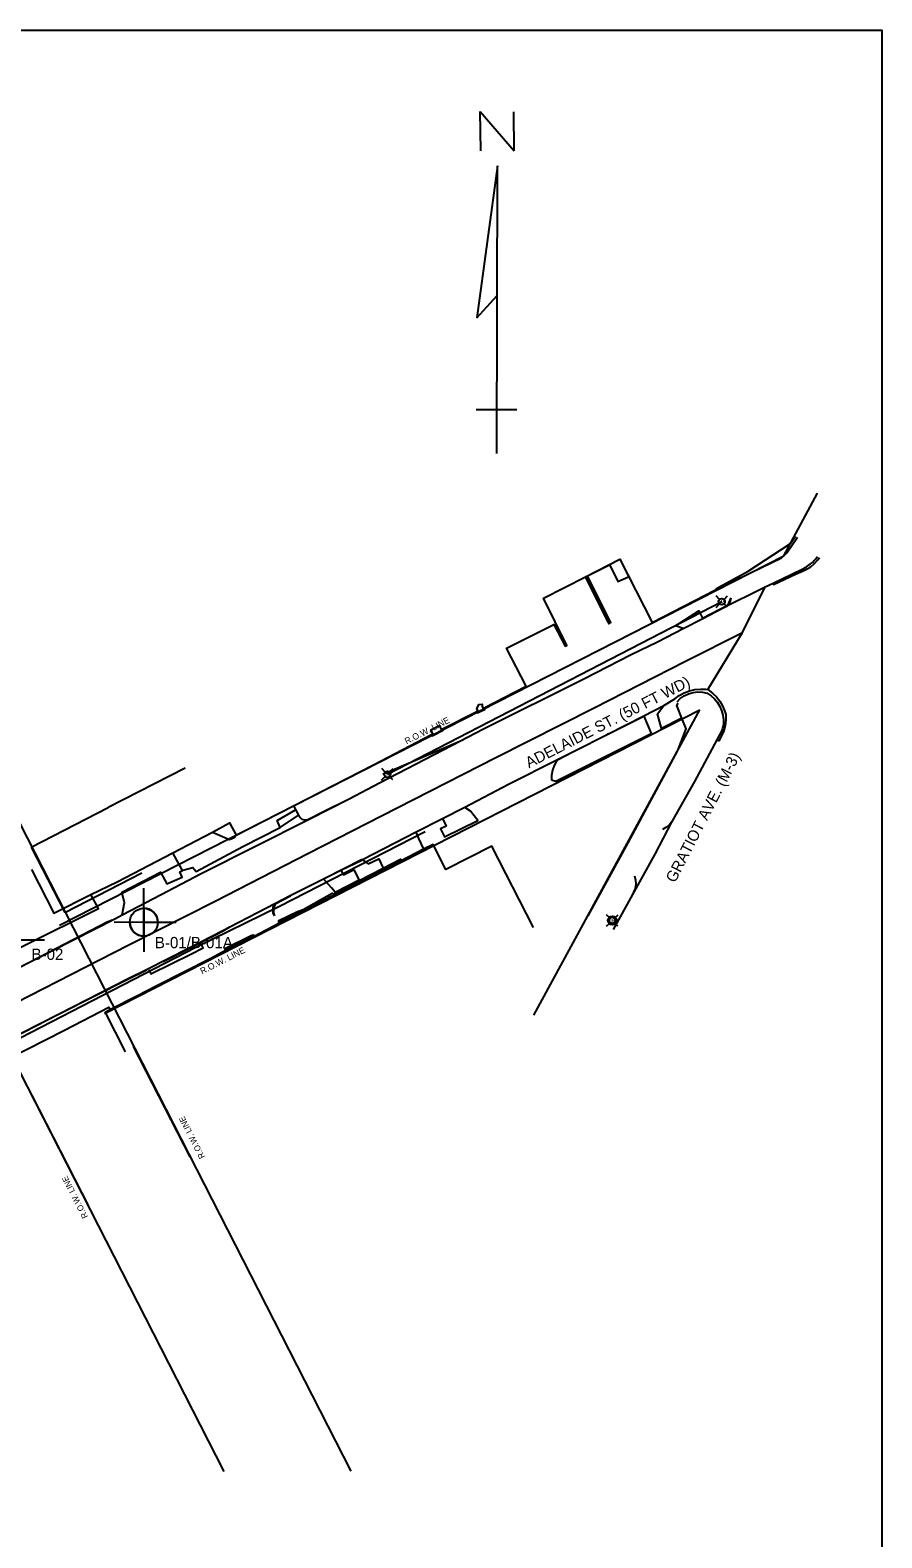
# Model space of a CAD drawing. Extents: x 19007.2 to 19038.3, y 21497.7 to 21516.9.
# Drawn here: x 19030.11 to 19036.52, y 21505.5 to 21516.85 of the extents above; entities that cross this region are included whole.
import ezdxf

# ---------------------------------------------------------------- set-up
doc = ezdxf.new("R2010")
doc.units = 0
for name, color, linetype in [('BORDER', 7, 'Continuous'), ('DETAIL_TEXT_DIMEN_PR', 7, 'Continuous'), ('G-ANNO-TTLB', 7, 'Continuous'), ('Level 14', 7, 'Continuous'), ('TYPICAL_TEXT_DIMEN_PR', 7, 'Continuous'), ('V-ANNO-TEXT', 7, 'Continuous'), ('V-BLDG-OTLN', 7, 'Continuous'), ('V-DEMO-PVMT', 7, 'Continuous'), ('V-PROP-RWAY', 7, 'Continuous'), ('V-PROP-RWAY-IDEN', 7, 'Continuous'), ('V-PVMT-CNTR', 7, 'Continuous'), ('V-PVMT-ROAD', 7, 'Continuous'), ('V-SITE-FENC', 7, 'Continuous'), ('V-SITE-STRS', 7, 'Continuous'), ('V-SITE-WALK', 7, 'Continuous'), ('V-UTIL-OVHD', 7, 'Continuous')]:
    doc.layers.add(name, color=color, linetype=linetype)

msp = doc.modelspace()

# ---------------------------------------------------------------- linework, layer by layer
at = {"layer": 'BORDER'}
for p, q in [((19033.498, 21515.945), (19033.494, 21516.24)), ((19033.494, 21516.24), (19033.749, 21515.944)), ((19033.749, 21515.944), (19033.748, 21516.239)), ((19033.624, 21515.833), (19033.469, 21514.688)), ((19033.618, 21513.666), (19033.624, 21515.833)), ((19033.469, 21514.688), (19033.621, 21514.855)), ((19033.769, 21513.994), (19033.464, 21513.995))]:
    msp.add_line(p, q, dxfattribs=at)
at = {"layer": 'G-ANNO-TTLB'}
msp.add_lwpolyline([(19036.518, 21497.739), (19007.175, 21497.739), (19007.175, 21516.854), (19036.518, 21516.854)], close=True, dxfattribs=at)
at = {"layer": 'Level 14'}
msp.add_circle((19034.489, 21510.149), 0.0328, dxfattribs=at)
at = {"layer": 'TYPICAL_TEXT_DIMEN_PR'}
for p, q in [((19030.961, 21510.136), (19030.961, 21510.393)), ((19030.961, 21510.136), (19030.738, 21510.135)), ((19030.961, 21510.136), (19030.961, 21509.912)), ((19030.961, 21510.136), (19031.205, 21510.136)), ((19029.97, 21510.003), (19030.214, 21510.004))]:
    msp.add_line(p, q, dxfattribs=at)
for points in [[(19030.961, 21510.241), (19030.961, 21510.136), (19031.067, 21510.136)], [(19030.961, 21510.03), (19030.961, 21510.136), (19030.856, 21510.135)]]:
    msp.add_lwpolyline(points, dxfattribs=at)
msp.add_circle((19030.961, 21510.136), 0.105, dxfattribs=at)
for start, end in [(0.0399, 90.0399), (180.0399, 270.0399)]:
    msp.add_arc((19030.961, 21510.136), 0.105, start, end, dxfattribs=at)
at = {"layer": 'V-BLDG-OTLN'}
for points in [[(19030.115, 21510.534), (19030.283, 21510.203), (19030.563, 21510.344), (19030.759, 21510.44), (19031.18, 21510.659), (19031.296, 21510.719), (19031.479, 21510.815), (19031.607, 21510.884), (19031.656, 21510.792), (19032.088, 21511.012), (19032.691, 21511.322), (19033.128, 21511.549), (19033.138, 21511.555), (19033.123, 21511.584), (19033.187, 21511.618), (19033.192, 21511.606), (19033.192, 21511.605), (19033.2, 21511.588), (19033.21, 21511.589), (19033.211, 21511.592), (19033.468, 21511.723), (19033.475, 21511.727), (19033.475, 21511.73), (19033.469, 21511.743), (19033.468, 21511.744), (19033.483, 21511.775), (19033.51, 21511.778), (19033.51, 21511.765), (19033.51, 21511.763), (19033.515, 21511.749), (19033.525, 21511.751), (19033.839, 21511.913), (19033.691, 21512.2), (19034.049, 21512.378), (19034.133, 21512.215), (19034.147, 21512.221), (19033.97, 21512.575), (19034.286, 21512.736), (19034.546, 21512.869), (19034.79, 21512.394), (19035.266, 21512.638)], [(19034.3, 21512.743), (19034.475, 21512.393), (19034.467, 21512.388), (19034.461, 21512.394), (19034.289, 21512.733)], [(19033.895, 21510.097), (19033.582, 21510.709), (19033.235, 21510.534), (19033.14, 21510.72), (19033.068, 21510.685), (19032.9, 21510.598), (19032.406, 21510.346), (19032.396, 21510.341), (19032.129, 21510.204), (19031.988, 21510.131), (19031.977, 21510.126), (19031.791, 21510.029), (19031.777, 21510.022), (19031.581, 21509.925), (19031.465, 21509.862), (19031.06, 21509.656), (19030.914, 21509.582), (19030.71, 21509.478), (19030.669, 21509.455), (19030.82, 21509.159)], [(19032.406, 21510.346), (19032.399, 21510.357), (19032.583, 21510.451), (19032.763, 21510.544), (19032.894, 21510.611), (19032.9, 21510.598)], [(19031.988, 21510.131), (19031.983, 21510.145), (19032.119, 21510.214), (19032.129, 21510.204)], [(19031.581, 21509.925), (19031.574, 21509.937), (19031.771, 21510.033), (19031.777, 21510.022)]]:
    msp.add_lwpolyline(points, dxfattribs=at)
at = {"layer": 'V-DEMO-PVMT'}
for points in [[(19028.193, 21508.862), (19028.458, 21508.995), (19028.585, 21509.06), (19028.712, 21509.125), (19029.395, 21509.474), (19030.111, 21509.839), (19030.748, 21510.163), (19030.799, 21510.192), (19031.091, 21510.345)], [(19028.204, 21509.012), (19028.449, 21509.137), (19028.713, 21509.274), (19029.337, 21509.592), (19029.504, 21509.674), (19030.06, 21509.961), (19030.619, 21510.24), (19030.563, 21510.344)], [(19030.796, 21510.363), (19030.867, 21510.399)], [(19030.799, 21510.192), (19030.815, 21510.285), (19030.796, 21510.363)], [(19028.651, 21509.186), (19028.68, 21509.16), (19028.723, 21509.133), (19029.394, 21509.477), (19030.11, 21509.841), (19030.685, 21510.139), (19030.722, 21510.155)], [(19028.4, 21508.455), (19028.813, 21508.662), (19029.367, 21508.959), (19029.601, 21509.079), (19030.324, 21509.447), (19030.834, 21509.706), (19030.982, 21509.779), (19031.298, 21509.941)], [(19030.999, 21509.778), (19031.013, 21509.747), (19031.319, 21509.898)], [(19031.106, 21509.839), (19031.299, 21509.938)], [(19029.358, 21508.819), (19029.354, 21508.84), (19029.36, 21508.93), (19029.373, 21508.96), (19029.602, 21509.076), (19030.323, 21509.445), (19030.835, 21509.705), (19030.983, 21509.777)]]:
    msp.add_lwpolyline(points, dxfattribs=at)
at = {"layer": 'V-PROP-RWAY'}
for p, q in [((19035.78, 21512.896), (19036.035, 21513.366)), ((19031.565, 21506), (19027.906, 21513.161)), ((19028.86, 21513.161), (19032.52, 21506.001)), ((19030.326, 21510.113), (19035.78, 21512.896)), ((19030.665, 21509.448), (19035.149, 21511.736)), ((19033.899, 21509.436), (19035.149, 21511.736)), ((19032.761, 21511.251), (19033.362, 21511.509)), ((19031.272, 21511.297), (19030.692, 21510.999)), ((19030.112, 21510.702), (19030.692, 21510.999)), ((19030.112, 21510.702), (19030.365, 21510.21)), ((19030.365, 21510.21), (19030.945, 21510.508)), ((19031.309, 21508.369), (19030.882, 21509.201)), ((19030.118, 21508.83), (19030.544, 21507.997))]:
    msp.add_line(p, q, dxfattribs=at)
at = {"layer": 'V-PVMT-CNTR'}
msp.add_lwpolyline([(19024.807, 21506.884), (19025.287, 21507.13), (19025.525, 21507.245), (19025.71, 21507.346), (19025.949, 21507.467), (19026.676, 21507.841), (19027.393, 21508.206), (19028.079, 21508.556), (19028.797, 21508.914), (19029.492, 21509.274), (19030.206, 21509.636), (19030.844, 21509.962), (19031.499, 21510.295), (19032.196, 21510.654), (19032.869, 21510.998), (19033.612, 21511.377), (19034.352, 21511.75), (19035.039, 21512.101), (19035.468, 21512.318)], dxfattribs=at)
at = {"layer": 'V-PVMT-ROAD'}
for points in [[(19031.091, 21510.345), (19031.394, 21510.504), (19032.205, 21510.911), (19032.507, 21511.066), (19032.735, 21511.186), (19033.282, 21511.469), (19033.519, 21511.591), (19034.274, 21511.968), (19034.631, 21512.151), (19034.828, 21512.248), (19035.023, 21512.347), (19035.17, 21512.423), (19035.367, 21512.526), (19035.58, 21512.631), (19035.641, 21512.662), (19035.699, 21512.689), (19035.703, 21512.678), (19035.868, 21512.757), (19035.925, 21512.783), (19035.957, 21512.796), (19035.975, 21512.807), (19035.987, 21512.815), (19036.009, 21512.835), (19036.037, 21512.866), (19036.049, 21512.883)], [(19034.286, 21512.736), (19034.463, 21512.384), (19034.478, 21512.393), (19034.303, 21512.744), (19034.468, 21512.828), (19034.531, 21512.701), (19034.611, 21512.737)], [(19035.701, 21512.69), (19035.918, 21512.794), (19035.95, 21512.812), (19035.981, 21512.834), (19035.996, 21512.846), (19036.01, 21512.86), (19036.018, 21512.869), (19036.033, 21512.891)], [(19035.208, 21511.888), (19035.468, 21512.318), (19035.641, 21512.662)], [(19035.169, 21512.425), (19035.361, 21512.525), (19035.385, 21512.579)], [(19035.368, 21512.529), (19035.379, 21512.556), (19035.385, 21512.579)], [(19031.298, 21509.941), (19031.385, 21509.986), (19031.557, 21510.074), (19031.609, 21510.101), (19031.811, 21510.206), (19031.952, 21510.28), (19032.063, 21510.336), (19032.315, 21510.463), (19032.324, 21510.467), (19032.599, 21510.608), (19032.607, 21510.608), (19033.011, 21510.816), (19033.21, 21510.917), (19033.378, 21511.002), (19033.708, 21511.175), (19034.075, 21511.361), (19034.191, 21511.42), (19034.459, 21511.555), (19034.45, 21511.55), (19034.726, 21511.689), (19034.876, 21511.769), (19034.959, 21511.818), (19034.992, 21511.843), (19035.029, 21511.864), (19035.069, 21511.879), (19035.11, 21511.888), (19035.152, 21511.892), (19035.194, 21511.89), (19035.208, 21511.888), (19035.244, 21511.862), (19035.273, 21511.834), (19035.298, 21511.801), (19035.318, 21511.765), (19035.33, 21511.736), (19035.343, 21511.701), (19035.344, 21511.659), (19035.339, 21511.616), (19035.328, 21511.575), (19035.328, 21511.574), (19035.29, 21511.502), (19035.278, 21511.509)], [(19034.976, 21511.795), (19035.001, 21511.82), (19035.031, 21511.841), (19035.063, 21511.857), (19035.097, 21511.867), (19035.132, 21511.871), (19035.168, 21511.869), (19035.203, 21511.861), (19035.203, 21511.861), (19035.233, 21511.841), (19035.259, 21511.818), (19035.282, 21511.791), (19035.299, 21511.76), (19035.311, 21511.73), (19035.322, 21511.694), (19035.326, 21511.661), (19035.325, 21511.627), (19035.318, 21511.594), (19035.313, 21511.58), (19035.107, 21511.196), (19034.935, 21510.889), (19034.808, 21510.648), (19034.64, 21510.345), (19034.496, 21510.08)], [(19035.013, 21511.672), (19034.86, 21511.596), (19034.83, 21511.705), (19034.876, 21511.769)], [(19033.128, 21511.549), (19033.133, 21511.539), (19033.215, 21511.582)], [(19034.45, 21511.55), (19034.726, 21511.687), (19034.782, 21511.557)], [(19034.075, 21511.358), (19034.191, 21511.418)], [(19032.088, 21511.012), (19032.126, 21510.942), (19032.128, 21510.939), (19032.138, 21510.924), (19032.152, 21510.913), (19032.17, 21510.908), (19032.188, 21510.908), (19032.196, 21510.91), (19032.314, 21510.969), (19032.507, 21511.066)], [(19031.254, 21510.528), (19031.329, 21510.548), (19031.354, 21510.518), (19031.707, 21510.705), (19031.988, 21510.848), (19032.126, 21510.942)], [(19031.988, 21510.848), (19031.966, 21510.901), (19032.102, 21510.983)], [(19033.21, 21510.917), (19033.238, 21510.86), (19033.196, 21510.839), (19033.226, 21510.778), (19033.475, 21510.902), (19033.422, 21510.972), (19033.387, 21510.995), (19033.378, 21511.002)], [(19031.479, 21510.815), (19031.606, 21510.759), (19031.641, 21510.773), (19031.656, 21510.792)], [(19033.011, 21510.809), (19033.03, 21510.766), (19033.068, 21510.685)], [(19034.935, 21510.889), (19034.916, 21510.867), (19034.893, 21510.848), (19034.868, 21510.835)], [(19031.023, 21510.479), (19031.087, 21510.512), (19031.133, 21510.424), (19031.249, 21510.474), (19031.231, 21510.516), (19031.253, 21510.526), (19031.18, 21510.659)], [(19032.324, 21510.467), (19032.444, 21510.527), (19032.608, 21510.606)], [(19032.608, 21510.606), (19032.651, 21510.575), (19032.731, 21510.613), (19032.763, 21510.544)], [(19030.867, 21510.399), (19031.023, 21510.479)], [(19032.401, 21510.363), (19032.373, 21510.394), (19032.315, 21510.463)], [(19032.402, 21510.362), (19032.582, 21510.454), (19032.544, 21510.533)], [(19032.444, 21510.527), (19032.464, 21510.493), (19032.544, 21510.533)], [(19034.656, 21510.484), (19034.664, 21510.453), (19034.665, 21510.422), (19034.66, 21510.391), (19034.649, 21510.362), (19034.64, 21510.345)], [(19031.579, 21509.923), (19031.572, 21509.938), (19031.769, 21510.037), (19031.784, 21510.042), (19031.791, 21510.029), (19031.977, 21510.126), (19031.978, 21510.148), (19032.118, 21510.216), (19032.161, 21510.232), (19032.379, 21510.354), (19032.396, 21510.341)], [(19031.947, 21510.184), (19031.94, 21510.207), (19031.939, 21510.231), (19031.944, 21510.255), (19031.955, 21510.276), (19031.956, 21510.277), (19032.065, 21510.335)], [(19031.945, 21510.183), (19031.936, 21510.203), (19031.933, 21510.226), (19031.936, 21510.248), (19031.944, 21510.269), (19031.952, 21510.28)], [(19032.129, 21510.201), (19032.089, 21510.181)], [(19031.299, 21509.938), (19031.387, 21509.983), (19031.558, 21510.072), (19031.609, 21510.101)], [(19031.319, 21509.898), (19031.408, 21509.942), (19031.387, 21509.983)]]:
    msp.add_lwpolyline(points, dxfattribs=at)
at = {"layer": 'V-SITE-FENC'}
msp.add_lwpolyline([(19035.269, 21512.647), (19035.513, 21512.779), (19035.83, 21512.987), (19035.869, 21513.042)], dxfattribs=at)
at = {"layer": 'V-SITE-STRS'}
for points in [[(19034.533, 21512.704), (19034.469, 21512.83)], [(19034.546, 21512.869), (19034.611, 21512.741)], [(19034.818, 21512.409), (19034.863, 21512.431)], [(19033.475, 21511.727), (19033.475, 21511.73), (19033.469, 21511.743), (19033.468, 21511.744), (19033.483, 21511.775), (19033.51, 21511.778), (19033.51, 21511.765), (19033.51, 21511.763), (19033.515, 21511.749), (19033.519, 21511.748), (19033.523, 21511.75)], [(19033.468, 21511.723), (19033.473, 21511.712), (19033.53, 21511.74), (19033.524, 21511.751)], [(19033.469, 21511.723), (19033.474, 21511.714), (19033.529, 21511.739), (19033.523, 21511.751)], [(19033.138, 21511.555), (19033.135, 21511.561), (19033.129, 21511.573), (19033.129, 21511.574), (19033.123, 21511.584), (19033.187, 21511.618), (19033.192, 21511.606), (19033.192, 21511.605), (19033.2, 21511.588), (19033.21, 21511.589)], [(19033.13, 21511.548), (19033.133, 21511.541), (19033.214, 21511.583), (19033.21, 21511.589)]]:
    msp.add_lwpolyline(points, dxfattribs=at)
at = {"layer": 'V-SITE-WALK'}
for points in [[(19035.268, 21512.638), (19035.529, 21512.766), (19035.764, 21512.879), (19035.803, 21512.917), (19035.884, 21513.036)], [(19035.023, 21512.347), (19034.964, 21512.367), (19035.14, 21512.482), (19035.169, 21512.425)], [(19034.307, 21510.184), (19034.608, 21510.735), (19034.981, 21511.43), (19035.046, 21511.591), (19035.013, 21511.672), (19034.974, 21511.769), (19034.985, 21511.786)], [(19034.03, 21511.207), (19034.064, 21511.199), (19034.526, 21511.429), (19034.782, 21511.557)], [(19034.075, 21511.358), (19034.069, 21511.349), (19034.051, 21511.315), (19034.038, 21511.28), (19034.031, 21511.242), (19034.03, 21511.207)], [(19029.358, 21508.817), (19029.503, 21508.901), (19029.646, 21508.959), (19030.363, 21509.323), (19030.698, 21509.496), (19030.71, 21509.478)]]:
    msp.add_lwpolyline(points, dxfattribs=at)
at = {"layer": 'V-UTIL-OVHD'}
for p, q in [((19035.297, 21512.566), (19035.27, 21512.593)), ((19035.27, 21512.506), (19035.297, 21512.533)), ((19035.33, 21512.566), (19035.356, 21512.593)), ((19035.355, 21512.508), (19035.33, 21512.533)), ((19032.778, 21511.266), (19032.752, 21511.293)), ((19032.812, 21511.266), (19032.838, 21511.293)), ((19032.751, 21511.206), (19032.778, 21511.233)), ((19032.837, 21511.208), (19032.812, 21511.233)), ((19034.445, 21510.105), (19034.472, 21510.132)), ((19034.472, 21510.166), (19034.446, 21510.192)), ((19034.505, 21510.166), (19034.532, 21510.192)), ((19034.53, 21510.107), (19034.505, 21510.132))]:
    msp.add_line(p, q, dxfattribs=at)
for points in [[(19032.795, 21511.25), (19035.313, 21512.55)], [(19026.134, 21507.192), (19026.9, 21507.642), (19027.163, 21507.77), (19027.837, 21508.125), (19029.41, 21508.947), (19031.347, 21509.945), (19031.982, 21510.257), (19033.079, 21510.818)]]:
    msp.add_lwpolyline(points, dxfattribs=at)
for centre in [(19035.313, 21512.55), (19032.795, 21511.25), (19034.489, 21510.149)]:
    msp.add_circle(centre, 0.0239, dxfattribs=at)

# ---------------------------------------------------------------- texts
at = {"layer": 'DETAIL_TEXT_DIMEN_PR'}
for s, p in [('B-01/B-01A', (19031.044, 21509.94)), ('B-02', (19030.115, 21509.852))]:
    msp.add_text(s, height=0.085, rotation=0.0399, dxfattribs=at).set_placement(p)
at = {"layer": 'V-ANNO-TEXT'}
for s, rotation, p in [('ADELAIDE ST. (50 FT WD)', 27.0313, (19033.861, 21511.294)), ('GRATIOT AVE. (M-3)', 62.8066, (19034.961, 21510.427))]:
    msp.add_text(s, height=0.08361, rotation=rotation, dxfattribs=at).set_placement(p)
at = {"layer": 'V-PROP-RWAY-IDEN'}
for height, rotation, p in [(0.04778, 27.0313, (19032.94, 21511.474)), (0.04778, 27.0313, (19031.4, 21509.742)), (0.04535, 117.1686, (19031.423, 21508.369)), (0.04535, 117.1686, (19030.542, 21507.919))]:
    msp.add_text('R.O.W. LINE', height=height, rotation=rotation, dxfattribs=at).set_placement(p)
at = {"layer": 'V-UTIL-OVHD'}
for s, height, p in [('M', 0.0239, (19035.305, 21512.538)), ('M', 0.0239, (19032.786, 21511.238)), ('LB', 0.0275, (19034.467, 21510.135)), ('M', 0.0239, (19034.48, 21510.137))]:
    msp.add_text(s, height=height, rotation=360, dxfattribs=at).set_placement(p)

doc.saveas('drawing.dxf')
